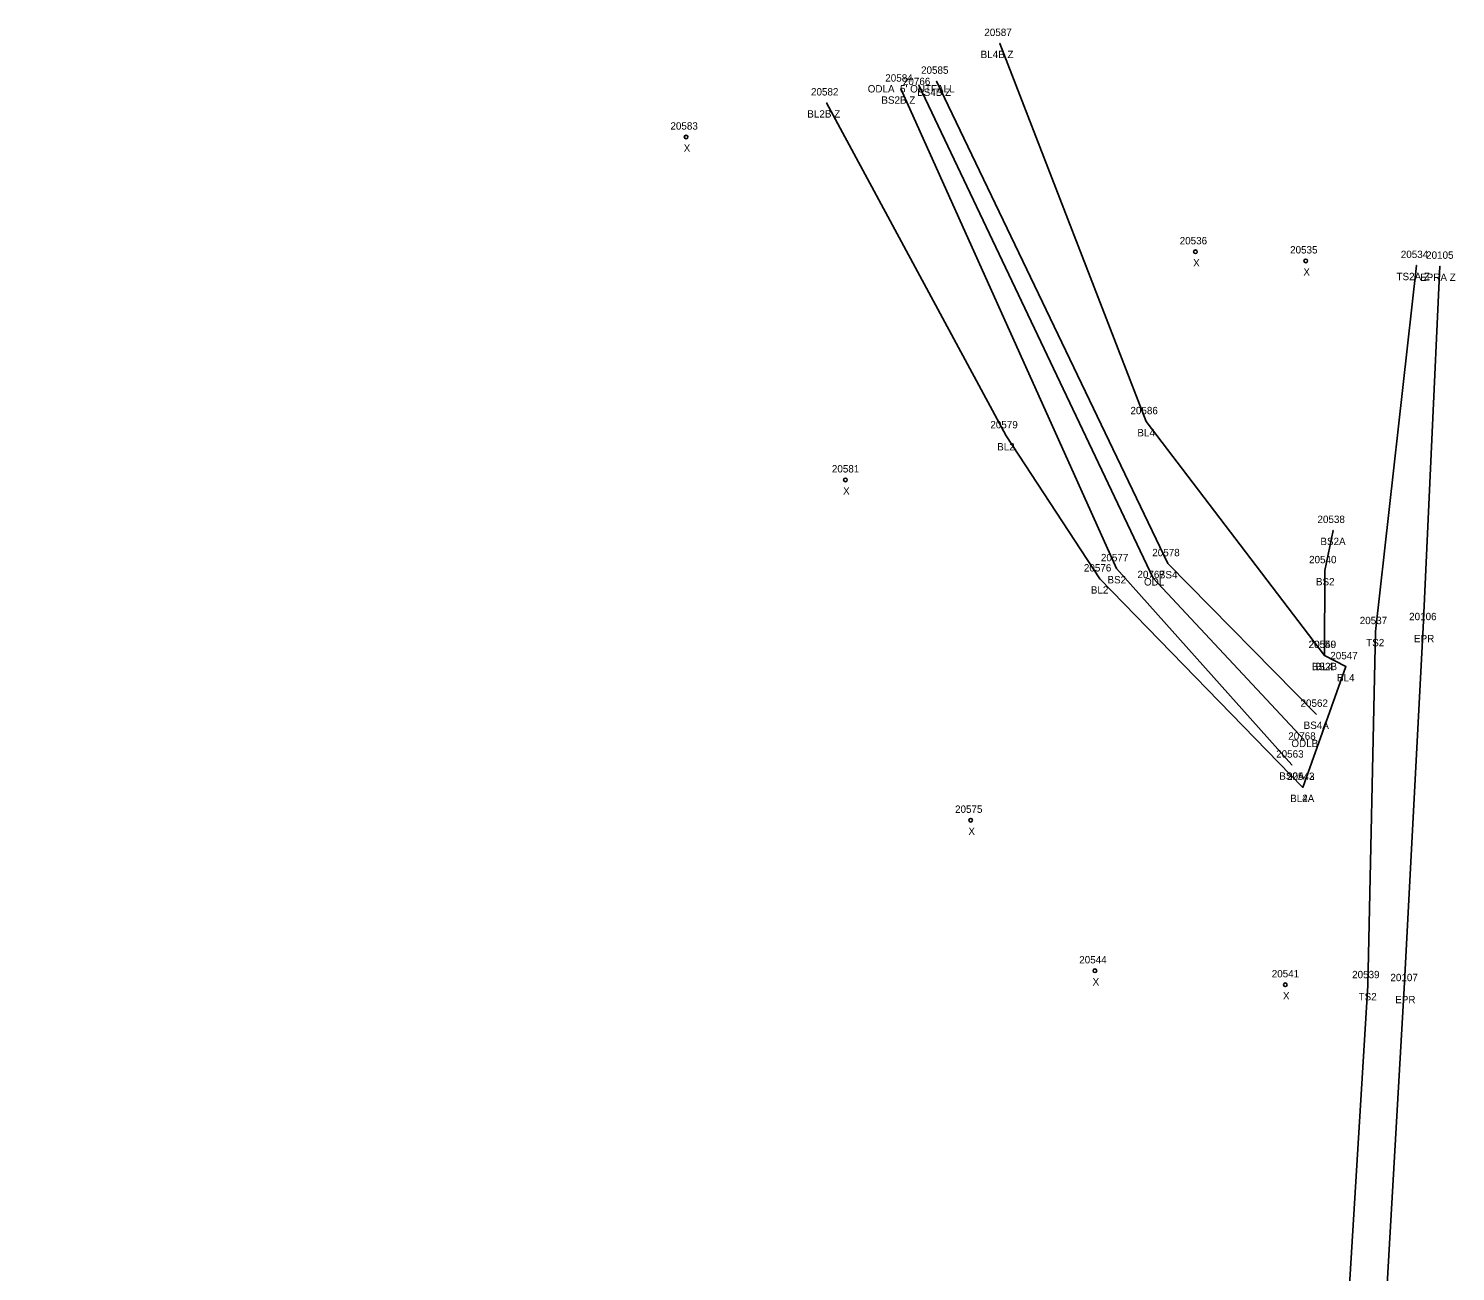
# Model space of a CAD drawing. Extents: x 1813127 to 1814107, y 1178171 to 1179078.
# Drawn here: x 1813477.1 to 1813670.6, y 1178909.4 to 1179078 of the extents above; entities that cross this region are included whole.
import ezdxf

# ---------------------------------------------------------------- set-up
doc = ezdxf.new("R2010")
doc.units = 0
for name, color, linetype in [('RD_DTM_BkLn1', 7, 'Continuous'), ('RD_DTM_BkLn2', 7, 'Continuous'), ('RD_EX_H2O', 7, 'Continuous'), ('RD_EX_H2O_txCode', 7, 'Continuous'), ('RD_EX_Road', 7, 'Continuous'), ('RD_EX_Road_txCode', 7, 'Continuous'), ('RD_SMD_Locator', 7, 'Continuous'), ('RD_SMD_Misc', 7, 'Continuous')]:
    doc.layers.add(name, color=color, linetype=linetype)

msp = doc.modelspace()

# ---------------------------------------------------------------- linework, layer by layer
at = {"layer": 'RD_DTM_BkLn1'}
for points in [[(1813649.87, 1178975.1), (1813655.73, 1178991.47), (1813652.81, 1178992.99), (1813628.65, 1179024.7), (1813608.82, 1179076)], [(1813649.87, 1178975.1), (1813622.34, 1179003.37), (1813609.64, 1179022.79), (1813585.32, 1179067.93)]]:
    msp.add_lwpolyline(points, dxfattribs=at)
at = {"layer": 'RD_DTM_BkLn2'}
for points in [[(1813651.71, 1178985.02), (1813631.59, 1179005.44), (1813600.23, 1179070.87)], [(1813648.41, 1178978.13), (1813624.62, 1179004.76), (1813595.38, 1179069.81)], [(1813665.28, 1179045.88), (1813659.72, 1178996.23), (1813658.69, 1178948.21), (1813655.81, 1178900.95), (1813653.1, 1178880.11)], [(1813653.99, 1179009.95), (1813652.89, 1179004.49), (1813652.81, 1178992.99)]]:
    msp.add_lwpolyline(points, dxfattribs=at)
at = {"layer": 'RD_EX_H2O'}
msp.add_lwpolyline([(1813597.83, 1179070.34), (1813629.6, 1179003.47), (1813650.05, 1178981.56)], dxfattribs=at)
at = {"layer": 'RD_EX_Road'}
msp.add_lwpolyline([(1813668.47, 1179045.78), (1813666.19, 1178996.77), (1813663.63, 1178947.81), (1813660.91, 1178900.64), (1813659.53, 1178882.12), (1813657.19, 1178859.48), (1813656.91, 1178851.42), (1813653.67, 1178829.82), (1813648.43, 1178809.53), (1813642.94, 1178796.31), (1813638.42, 1178791.25), (1813631.39, 1178785.04), (1813613.59, 1178777.71), (1813596.09, 1178775.31), (1813522.62, 1178785.74), (1813518.21, 1178785.19), (1813499.47, 1178787.87), (1813450.56, 1178796.06)], dxfattribs=at)
at = {"layer": 'RD_SMD_Locator'}
for centre, radius in [((1813608.82, 1179076), 0.001), ((1813597.83, 1179070.34), 0.001), ((1813600.23, 1179070.87), 0.001), ((1813595.38, 1179069.81), 0.001), ((1813585.32, 1179067.93), 0.001), ((1813566.26, 1179063.3), 0.25), ((1813635.33, 1179047.74), 0.25), ((1813650.28, 1179046.5), 0.25), ((1813665.28, 1179045.88), 0.001), ((1813668.47, 1179045.78), 0.001), ((1813628.65, 1179024.7), 0.001), ((1813609.64, 1179022.79), 0.001), ((1813587.86, 1179016.8), 0.25), ((1813653.99, 1179009.95), 0.001), ((1813624.62, 1179004.76), 0.001), ((1813631.59, 1179005.44), 0.001), ((1813652.89, 1179004.49), 0.001), ((1813622.34, 1179003.37), 0.001), ((1813629.6, 1179003.47), 0.001), ((1813666.19, 1178996.77), 0.001), ((1813659.72, 1178996.23), 0.001), ((1813652.81, 1178992.99), 0.001), ((1813652.81, 1178992.99), 0.001), ((1813655.73, 1178991.47), 0.001), ((1813651.71, 1178985.02), 0.001), ((1813650.05, 1178981.56), 0.001), ((1813648.41, 1178978.13), 0.001), ((1813649.87, 1178975.1), 0.001), ((1813649.87, 1178975.1), 0.001), ((1813604.85, 1178970.64), 0.25), ((1813621.69, 1178950.22), 0.25), ((1813647.51, 1178948.33), 0.25), ((1813658.69, 1178948.21), 0.001), ((1813663.63, 1178947.81), 0.001)]:
    msp.add_circle(centre, radius, dxfattribs=at)

# ---------------------------------------------------------------- texts
at = {"layer": 'RD_EX_H2O_txCode'}
for s, p in [("ODLA  5' OUTFALL", (1813590.89, 1179069.34)), ('20766', (1813595.66, 1179070.34)), ('20767', (1813627.46, 1179003.47)), ('ODL', (1813628.35, 1179002.47)), ('20768', (1813647.91, 1178981.56)), ('ODLB', (1813648.33, 1178980.56))]:
    msp.add_text(s, height=1, dxfattribs=at).set_placement(p)
at = {"layer": 'RD_EX_Road_txCode'}
for s, p in [('20105', (1813666.6, 1179046.78)), ('EPRA Z', (1813665.79, 1179043.78)), ('20106', (1813664.3, 1178997.77)), ('EPR', (1813664.96, 1178994.77)), ('20107', (1813661.76, 1178948.81)), ('EPR', (1813662.41, 1178945.81))]:
    msp.add_text(s, height=1, dxfattribs=at).set_placement(p)
at = {"layer": 'RD_SMD_Misc'}
for s, p in [('20587', (1813606.7, 1179077)), ('BL4B Z', (1813606.2, 1179074)), ('20585', (1813598.12, 1179071.87)), ('20584', (1813593.27, 1179070.81)), ('20582', (1813583.2, 1179068.93)), ('BS2B Z', (1813592.74, 1179067.81)), ('BS4B Z', (1813597.59, 1179068.87)), ('BL2B Z', (1813582.7, 1179065.93)), ('20583', (1813564.14, 1179064.3)), ('X', (1813565.94, 1179061.3)), ('20536', (1813633.19, 1179048.74)), ('20535', (1813648.16, 1179047.5)), ('20534', (1813663.17, 1179046.88)), ('X', (1813635.01, 1179045.74)), ('X', (1813649.96, 1179044.5)), ('TS2A Z', (1813662.59, 1179043.88)), ('20586', (1813626.51, 1179025.7)), ('20579', (1813607.52, 1179023.79)), ('BL4', (1813627.45, 1179022.7)), ('BL2', (1813608.44, 1179020.79)), ('20581', (1813586.03, 1179017.8)), ('X', (1813587.55, 1179014.8)), ('20538', (1813651.87, 1179010.95)), ('BS2A', (1813652.27, 1179007.95)), ('20577', (1813622.51, 1179005.76)), ('20578', (1813629.47, 1179006.44)), ('20540', (1813650.73, 1179005.49)), ('20576', (1813620.2, 1179004.37)), ('BS4', (1813630.36, 1179003.44)), ('BL2', (1813621.14, 1179001.37)), ('BS2', (1813623.4, 1179002.76)), ('BS2', (1813651.66, 1179002.49)), ('20537', (1813657.6, 1178997.23)), ('20550', (1813650.66, 1178993.99)), ('20549', (1813650.69, 1178993.99)), ('TS2', (1813658.47, 1178994.23)), ('20547', (1813653.61, 1178992.47)), ('BS2B', (1813651.11, 1178990.99)), ('BL4', (1813651.61, 1178990.99)), ('BL4', (1813654.52, 1178989.47)), ('20562', (1813649.57, 1178986.02)), ('BS4A', (1813650, 1178983.02)), ('20563', (1813646.27, 1178979.13)), ('BS2A', (1813646.69, 1178976.13)), ('20542', (1813647.75, 1178976.1)), ('20543', (1813647.75, 1178976.1)), ('BL2A', (1813648.17, 1178973.1)), ('BL4A', (1813648.17, 1178973.1)), ('20575', (1813602.73, 1178971.64)), ('X', (1813604.54, 1178968.64)), ('20544', (1813619.57, 1178951.22)), ('20541', (1813645.67, 1178949.33)), ('20539', (1813656.57, 1178949.21)), ('X', (1813621.38, 1178948.22)), ('X', (1813647.19, 1178946.33)), ('TS2', (1813657.45, 1178946.21))]:
    msp.add_text(s, height=1, dxfattribs=at).set_placement(p)

doc.saveas('drawing.dxf')
